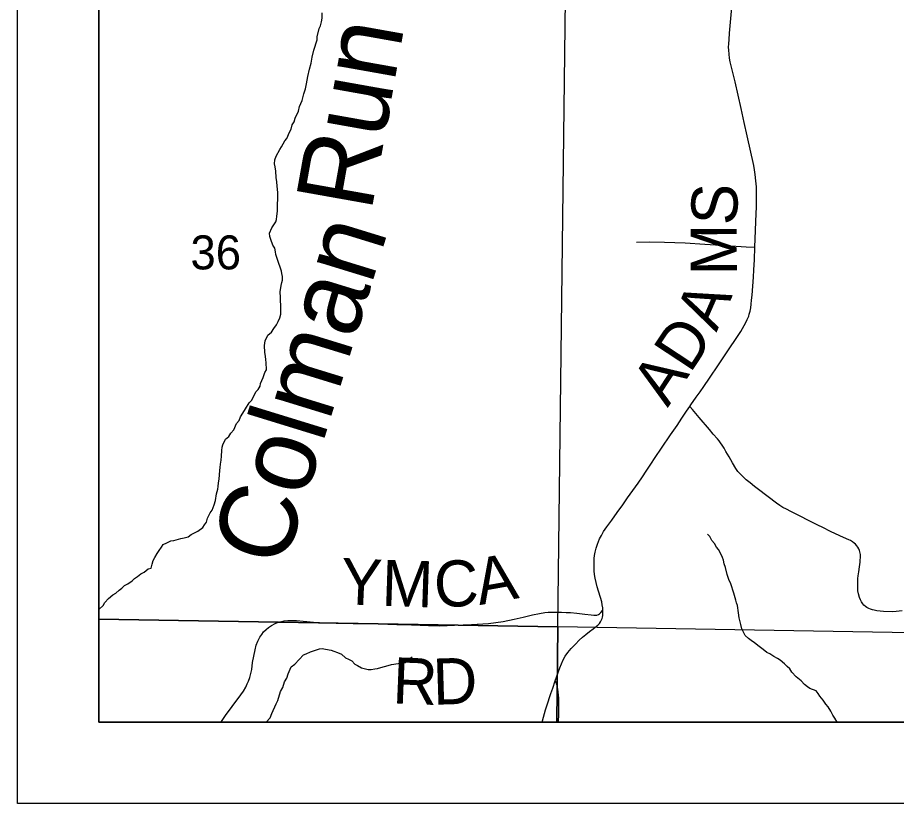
# Model space of a CAD drawing. Extents: x 0 to 34, y 0 to 22.
# Drawn here: x 18.5 to 19.582, y 13.5 to 14.468 of the extents above; entities that cross this region are included whole.
import ezdxf

# ---------------------------------------------------------------- set-up
doc = ezdxf.new("R2010")
doc.units = 0
for name, color, linetype in [('GM_X_Corporation', 7, 'Continuous'), ('GM_X_Minor_River', 7, 'Continuous'), ('GM_X_Minor_River_Text', 7, 'Continuous'), ('GM_X_Section_Text', 7, 'Continuous'), ('GM_X_Township_Road', 7, 'Continuous'), ('GM_X_Township_Road_Text', 7, 'Continuous'), ('SH_Data', 7, 'Continuous')]:
    doc.layers.add(name, color=color, linetype=linetype)

msp = doc.modelspace()

# ---------------------------------------------------------------- linework, layer by layer
at = {"layer": 'GM_X_Corporation'}
for points in [[(18.6, 14.6612), (18.6, 13.7267), (19.1654, 13.7176), (19.1768, 14.6588)], [(18.6, 14.6606), (18.6, 13.6), (24.2109, 13.6), (24.2228, 14.2453), (24.2265, 14.4444), (24.2301, 14.5912), (22.9003, 14.6033), (22.3464, 14.612), (21.314, 14.623), (21.1282, 14.6279), (20.2571, 14.6508), (20.2016, 14.6512), (19.8855, 14.6528), (19.4007, 14.6554), (18.9216, 14.6592)], [(19.1768, 14.6588), (20.2028, 14.6536), (20.1822, 13.7001), (19.1654, 13.7176)], [(18.6, 13.7267), (18.6, 13.6), (19.1641, 13.6), (19.1654, 13.7176)], [(19.1641, 13.6), (20.1804, 13.6), (20.1822, 13.7001), (19.1654, 13.7176)]]:
    msp.add_lwpolyline(points, close=True, dxfattribs=at)
at = {"layer": 'GM_X_Minor_River'}
for points in [[(18.7993, 14.0169), (18.8025, 14.0246), (18.8046, 14.0304), (18.8065, 14.0338), (18.8062, 14.043), (18.8058, 14.046), (18.8053, 14.0505), (18.8044, 14.0551), (18.8042, 14.0638), (18.8048, 14.0696), (18.8081, 14.0765), (18.8129, 14.0804), (18.8155, 14.0847), (18.8188, 14.0893), (18.821, 14.0932), (18.8231, 14.0978), (18.8241, 14.1024), (18.8243, 14.1096), (18.8242, 14.1138), (18.8238, 14.1184), (18.8237, 14.1229), (18.8235, 14.1298), (18.8244, 14.1378), (18.8255, 14.1412), (18.8262, 14.1443), (18.8261, 14.1489), (18.8256, 14.1523), (18.8252, 14.1553), (18.8236, 14.1591), (18.8215, 14.1659), (18.8194, 14.1723), (18.8182, 14.1757), (18.8178, 14.1791), (18.8169, 14.1837), (18.8145, 14.1874), (18.8117, 14.1942), (18.8105, 14.198), (18.8104, 14.2021), (18.8133, 14.2087), (18.818, 14.216), (18.8187, 14.2191), (18.8194, 14.2229), (18.82, 14.229), (18.8199, 14.2324), (18.8201, 14.2385), (18.8204, 14.2431), (18.8207, 14.2473), (18.8206, 14.2522), (18.8196, 14.2598), (18.8191, 14.2652), (18.8186, 14.2708), (18.8181, 14.2785), (18.8172, 14.2838), (18.8163, 14.2875), (18.8166, 14.2925), (18.8184, 14.2971), (18.8231, 14.3052), (18.8249, 14.3083), (18.8293, 14.3156), (18.8315, 14.3187), (18.8347, 14.3264), (18.8369, 14.3303), (18.8383, 14.3356), (18.8405, 14.3391), (18.8419, 14.3437), (18.8459, 14.3522), (18.8472, 14.3579), (18.8505, 14.3656), (18.8526, 14.3737), (18.8547, 14.3798), (18.8557, 14.3859), (18.8573, 14.3951), (18.8594, 14.4039), (18.8615, 14.4116), (18.8628, 14.4188), (18.8649, 14.4276), (18.8688, 14.4403), (18.8691, 14.4437), (18.8715, 14.4541), (18.8729, 14.4575), (18.8743, 14.4621), (18.875, 14.4667), (18.8752, 14.4732)], [(18.6, 13.7386), (18.6002, 13.7389), (18.6054, 13.7436), (18.6076, 13.7475), (18.612, 13.7521), (18.6172, 13.7568), (18.621, 13.7588), (18.625, 13.7627), (18.6284, 13.7651), (18.6317, 13.7682), (18.6358, 13.7702), (18.6411, 13.7741), (18.644, 13.7769), (18.6477, 13.7793), (18.6518, 13.7828), (18.6559, 13.7848), (18.6608, 13.7887), (18.6645, 13.7896), (18.6656, 13.7945), (18.667, 13.7991), (18.6692, 13.8026), (18.6717, 13.8076), (18.6742, 13.8115), (18.6772, 13.8153), (18.6794, 13.8188), (18.6839, 13.8208), (18.6887, 13.8232), (18.6925, 13.8237), (18.7012, 13.8262), (18.7053, 13.8271), (18.7102, 13.8283), (18.7139, 13.8311), (18.7218, 13.8351), (18.7281, 13.8398), (18.7303, 13.8429), (18.7325, 13.8464), (18.7339, 13.8513), (18.7372, 13.8579), (18.7397, 13.861), (18.7419, 13.8675), (18.7436, 13.8729), (18.7449, 13.8813), (18.7467, 13.887), (18.747, 13.8901), (18.7476, 13.8947), (18.7483, 13.8992), (18.7485, 13.9046), (18.7492, 13.9099), (18.7495, 13.9134), (18.7498, 13.9175), (18.7508, 13.9225), (18.751, 13.9275), (18.7516, 13.9347), (18.7519, 13.9385), (18.7526, 13.9416), (18.7562, 13.9485), (18.7603, 13.9517), (18.7625, 13.9559), (18.7662, 13.9598), (18.7698, 13.9679), (18.7727, 13.9714), (18.7745, 13.976), (18.7774, 13.9806), (18.7807, 13.986), (18.7851, 13.9934), (18.7884, 13.9965), (18.7935, 14.0069), (18.7964, 14.0096), (18.7986, 14.0139), (18.7993, 14.0169)], [(19.5017, 13.6134), (19.4982, 13.6191), (19.4954, 13.6224), (19.4919, 13.6273), (19.488, 13.6321), (19.4857, 13.6355), (19.4833, 13.6385), (19.4757, 13.6414), (19.4726, 13.6436), (19.4691, 13.6465), (19.4648, 13.651), (19.459, 13.6558), (19.4536, 13.6614), (19.4509, 13.6655), (19.4477, 13.6685), (19.4446, 13.6718), (19.4392, 13.6763), (19.4358, 13.6785), (19.4312, 13.681), (19.4262, 13.6843), (19.4227, 13.6858), (19.4181, 13.6895), (19.4134, 13.6932), (19.4073, 13.6976), (19.4034, 13.7005), (19.4, 13.7031), (19.3961, 13.7068), (19.3921, 13.7151), (19.3905, 13.7204), (19.3887, 13.7287), (19.3878, 13.7348), (19.3865, 13.7435), (19.3853, 13.7469), (19.3844, 13.7503), (19.382, 13.759), (19.3783, 13.7703), (19.3759, 13.7756), (19.3738, 13.782), (19.3717, 13.7904), (19.3701, 13.7949), (19.3692, 13.7994), (19.368, 13.8028), (19.3664, 13.8066), (19.3632, 13.8126), (19.3605, 13.8156), (19.3581, 13.8201), (19.355, 13.8238), (19.3523, 13.8287), (19.3495, 13.8317)], [(18.8062, 13.6), (18.811, 13.6054), (18.8131, 13.6108), (18.8185, 13.6227), (18.8203, 13.6266), (18.8239, 13.6377), (18.8268, 13.6427), (18.8289, 13.6496), (18.8314, 13.6543), (18.8332, 13.6596), (18.8368, 13.6681), (18.8416, 13.6716), (18.8523, 13.6829), (18.8553, 13.6841), (18.8606, 13.6865), (18.867, 13.6886)], [(18.867, 13.6886), (18.8719, 13.6902), (18.8749, 13.6907), (18.8794, 13.69), (18.8863, 13.6887), (18.8893, 13.6876), (18.8939, 13.6858), (18.8989, 13.6836), (18.9039, 13.6792), (18.9074, 13.6778), (18.9116, 13.6756), (18.9155, 13.6715), (18.9185, 13.67), (18.9235, 13.6671), (18.9319, 13.665), (18.9353, 13.6647), (18.9399, 13.6656), (18.9433, 13.6661), (18.9474, 13.6673), (18.9564, 13.6698), (18.9606, 13.671), (18.9685, 13.6724), (18.9734, 13.6729), (18.9779, 13.6733), (18.9816, 13.6772), (18.9861, 13.6804)], [(19.5093, 13.6), (19.5065, 13.6048), (19.5041, 13.6085), (19.5017, 13.6134)]]:
    msp.add_lwpolyline(points, dxfattribs=at)
at = {"layer": 'GM_X_Township_Road'}
for points in [[(19.4066, 14.1568), (19.4074, 14.1693), (19.4081, 14.1847), (19.4097, 14.2265), (19.4099, 14.2341), (19.4101, 14.2434), (19.41, 14.2509), (19.4098, 14.2593), (19.4093, 14.2667), (19.4085, 14.2745), (19.4077, 14.28), (19.4067, 14.2853), (19.3986, 14.3221), (19.3949, 14.3385), (19.3912, 14.3555), (19.3838, 14.3884), (19.3776, 14.413), (19.3768, 14.4176), (19.3761, 14.4227), (19.3757, 14.4274), (19.3755, 14.4311), (19.3758, 14.4354), (19.3761, 14.4406), (19.3768, 14.4484), (19.3794, 14.4798)], [(19.262, 14.1912), (19.2777, 14.1913), (19.2966, 14.191), (19.3221, 14.19), (19.3464, 14.1887), (19.3723, 14.1871), (19.3972, 14.1854), (19.4081, 14.1847)], [(19.2208, 13.7378), (19.2206, 13.741), (19.2201, 13.7446), (19.2194, 13.7481), (19.2138, 13.7665), (19.2124, 13.7721), (19.2113, 13.7772), (19.2104, 13.7819), (19.21, 13.7864), (19.2099, 13.7915), (19.21, 13.7976), (19.2101, 13.8014), (19.2106, 13.8053), (19.2113, 13.8095), (19.2124, 13.8143), (19.2142, 13.8194), (19.2166, 13.8256), (19.219, 13.83), (19.2217, 13.8349), (19.2258, 13.8407), (19.2317, 13.8489), (19.2384, 13.8581), (19.2452, 13.8676), (19.2513, 13.8762), (19.2644, 13.8945), (19.2695, 13.9022), (19.2739, 13.909), (19.2797, 13.9179), (19.2851, 13.9259), (19.2928, 13.9372), (19.3042, 13.9539), (19.3121, 13.9654), (19.3182, 13.9745), (19.3238, 13.9828), (19.3279, 13.9888), (19.3293, 13.9909), (19.3357, 14), (19.3404, 14.0067), (19.3452, 14.0135), (19.3521, 14.0235), (19.3632, 14.0399), (19.3732, 14.0548), (19.3881, 14.0772), (19.3906, 14.0812), (19.3969, 14.0923), (19.3986, 14.0957), (19.4004, 14.1), (19.4011, 14.1024), (19.402, 14.1059), (19.4029, 14.1101), (19.4035, 14.1147), (19.404, 14.1198), (19.4046, 14.1259), (19.4061, 14.1481), (19.4066, 14.1568)], [(19.5171, 13.8276), (19.5071, 13.8321), (19.5011, 13.8349), (19.4917, 13.8396), (19.4856, 13.8426), (19.4524, 13.8593), (19.4468, 13.8621), (19.4425, 13.8645), (19.4385, 13.867), (19.4347, 13.8695), (19.4123, 13.8865), (19.4076, 13.8902), (19.402, 13.8946), (19.3971, 13.8984), (19.393, 13.9024), (19.3901, 13.9052), (19.3871, 13.9085), (19.3844, 13.9124), (19.3805, 13.9193), (19.3765, 13.9268), (19.3723, 13.9334), (19.37, 13.9374), (19.3677, 13.941), (19.3656, 13.944), (19.3639, 13.9464), (19.3621, 13.9487), (19.3568, 13.9548), (19.3519, 13.9605), (19.3394, 13.9751), (19.3312, 13.9849), (19.3279, 13.9888)], [(19.5893, 13.737), (19.5821, 13.7363), (19.5778, 13.736), (19.5664, 13.7362), (19.5582, 13.7373), (19.555, 13.7379), (19.5529, 13.7384), (19.5505, 13.7391), (19.5484, 13.74), (19.546, 13.7411), (19.544, 13.7425), (19.5423, 13.7442), (19.5409, 13.7459), (19.5393, 13.7483), (19.5379, 13.7507), (19.5368, 13.7535), (19.5355, 13.758), (19.5349, 13.7618), (19.5346, 13.7663), (19.5347, 13.7736), (19.5349, 13.7769), (19.5353, 13.7804), (19.5359, 13.7852), (19.5366, 13.7912), (19.5375, 13.7972), (19.5378, 13.7999), (19.538, 13.8025), (19.5379, 13.8066), (19.5373, 13.8097), (19.5367, 13.8116), (19.5359, 13.8136), (19.5349, 13.8155), (19.5336, 13.8172), (19.532, 13.819), (19.5303, 13.8204), (19.5281, 13.822), (19.5256, 13.8236), (19.5235, 13.8247), (19.5171, 13.8276)], [(18.7506, 13.6), (18.7512, 13.601), (18.7562, 13.6082), (18.7644, 13.6193), (18.775, 13.6338), (18.7781, 13.6383), (18.7809, 13.6432), (18.7829, 13.6471), (18.7844, 13.6504), (18.7861, 13.655), (18.7874, 13.6598), (18.7883, 13.6648), (18.7895, 13.6736), (18.7908, 13.6813), (18.7924, 13.6889), (18.794, 13.6948), (18.7959, 13.6996), (18.7985, 13.7046), (18.8007, 13.7081), (18.803, 13.7112), (18.8061, 13.7142), (18.8088, 13.7164), (18.8128, 13.7191), (18.8172, 13.7215), (18.8202, 13.7228), (18.8229, 13.7236), (18.8254, 13.7241), (18.8283, 13.7247), (18.833, 13.7252), (18.8378, 13.7254), (18.8433, 13.7251), (18.8646, 13.7232), (18.8793, 13.7224), (18.8923, 13.7219), (18.9131, 13.7217), (18.929, 13.7215), (18.9443, 13.721), (18.9671, 13.7203), (18.9853, 13.7197), (18.9958, 13.7193), (19.0059, 13.719), (19.0201, 13.7188), (19.0382, 13.7193), (19.059, 13.7202), (19.08, 13.7215), (19.098, 13.7238), (19.1115, 13.7268), (19.1226, 13.7293), (19.1341, 13.732), (19.1429, 13.734), (19.1495, 13.7349), (19.1536, 13.7353), (19.1585, 13.7355), (19.1645, 13.7356), (19.1697, 13.7355), (19.1754, 13.7352), (19.1809, 13.735), (19.1888, 13.7342), (19.1986, 13.733), (19.2065, 13.732), (19.2097, 13.7318), (19.2115, 13.7317), (19.2135, 13.7319), (19.2152, 13.7325), (19.2168, 13.7336), (19.2183, 13.7351), (19.2208, 13.7378)], [(19.1461, 13.6), (19.1465, 13.6015), (19.1489, 13.6109), (19.1502, 13.6151), (19.1517, 13.6202), (19.1567, 13.6353), (19.159, 13.642), (19.1622, 13.6511), (19.1679, 13.6668), (19.1697, 13.6718), (19.1719, 13.6768), (19.1744, 13.6814), (19.1776, 13.686), (19.1818, 13.6908), (19.1869, 13.6961), (19.1917, 13.7008), (19.1956, 13.7045), (19.1998, 13.7081), (19.2044, 13.7118), (19.2088, 13.715), (19.2129, 13.7181), (19.2146, 13.7196), (19.2165, 13.7216), (19.2178, 13.7234), (19.2188, 13.7252), (19.2198, 13.7277), (19.2202, 13.7292), (19.2206, 13.7312), (19.2207, 13.7337), (19.2208, 13.7378)], [(19.1661, 13.6), (19.1666, 13.6102), (19.1667, 13.6171), (19.1666, 13.6223), (19.1664, 13.6301), (19.1662, 13.6332), (19.1657, 13.6375), (19.1652, 13.6404), (19.1647, 13.643), (19.1643, 13.6451), (19.1636, 13.6474), (19.1631, 13.6487), (19.1626, 13.6501), (19.1622, 13.6511)]]:
    msp.add_lwpolyline(points, dxfattribs=at)
at = {"layer": 'SH_Data'}
for points in [[(18.5, 20.5), (25.5, 20.5), (25.5, 13.5), (18.5, 13.5)], [(18.6, 20.4), (25.4, 20.4), (25.4, 13.6), (18.6, 13.6)]]:
    msp.add_lwpolyline(points, close=True, dxfattribs=at)

# ---------------------------------------------------------------- texts
at = {"layer": 'GM_X_Minor_River_Text'}
for s, height, rotation, p in [('Run', 0.09472, 79.8985, (18.9355, 14.2271)), ('Colman', 0.0947, 72.905, (18.828, 13.7873))]:
    msp.add_text(s, height=height, rotation=rotation, dxfattribs=at).set_placement(p)
at = {"layer": 'GM_X_Section_Text'}
msp.add_text('36', height=0.04186, rotation=0, dxfattribs=at).set_placement((18.7129, 14.1575))
at = {"layer": 'GM_X_Township_Road_Text'}
for s, rotation, p in [('S', 87.4904, (19.3855, 14.2113)), ('M', 90.206, (19.3858, 14.1503)), ('A', 66.4141, (19.3606, 14.0794)), ('D', 56.6683, (19.3281, 14.0284)), ('A', 56.6534, (19.3006, 13.9866)), ('Y', 357.3435, (18.8968, 13.7456)), ('M', 358.1386, (18.9477, 13.7433)), ('C', 2.3731, (19.0139, 13.7413)), ('A', 10.0495, (19.0688, 13.7441)), ('R', 357.6654, (18.9611, 13.6233)), ('D', 1.7707, (19.0121, 13.6214))]:
    msp.add_text(s, height=0.0568, rotation=rotation, dxfattribs=at).set_placement(p)

doc.saveas('drawing.dxf')
